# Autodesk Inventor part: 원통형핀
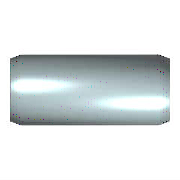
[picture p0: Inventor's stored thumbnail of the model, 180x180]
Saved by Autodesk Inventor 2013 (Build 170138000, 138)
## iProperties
IsCustomPart: 1
Created: 2012-02
Part Number: 원통형핀
Material: 강철, 연강
Description: 평행 핀
Document SubType Name: Modeling
Standard: KS B 1320
Designer: mduedu
Standards Organization: KS
Language: ko-KR
Size Designation: B 2 x  14
Categories: <MemberInstance><Categories><Category DisplayName="조임쇠" InternalName="e4da775c-781d-43d5-af7c-5136215cf5a6" Mnemonic="FSTN"><Category DisplayName="핀" InternalNa
Density: 1 g/cm^3
Author: mduedu
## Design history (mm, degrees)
sketch "스케치"
  geometry: C1 r 1 at (0, 0); 1 further point
  constraints: 1 centre point, 1 coincident
  dimensions: "d1" = 2 diameter of C1 (= NND)
extrude "본체" new body sketch "스케치" distance "d2" = 14 (= NLG); taper "d3" = 0 deg
chamfer "스케치2" distance "d8" = 0.35 (= PHH); stored, may be unused: angle "d9" = 15 deg (= FAWI), second distance "d12" = 0.35 (= PHH)
node "작업 평면1"
body "Solid1"
chamfer "모따기1" distance "d4" = 0.35 (= PHH); stored, may be unused: angle "d5" = 15 deg (= FAWI), second distance "d11" = 0.35 (= PHH)
other parameters: "NND" = 2 [user parameter; used in 1 equation term], "NLG" = 14 [user parameter; used in 1 equation term], "PHH" = 0.35 [user parameter; used in 4 equation terms], "FAWI" = 15 deg [user parameter; used in 2 equation terms], "d13" = 0, "d15" = 0, "d16" = 0, "KAH" = 0.25 [user parameter]
